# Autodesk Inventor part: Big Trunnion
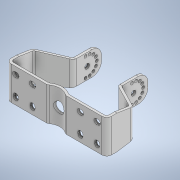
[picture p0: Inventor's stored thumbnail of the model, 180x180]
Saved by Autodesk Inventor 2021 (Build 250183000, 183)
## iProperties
Created: 2020-07
Part Number: Big Trunnion
Material: Generic
Document SubType Name: Modeling
Designer: DarrinWoodcock
Density: 1 g/cm^3
Appearance: Default
Title: 000
Author: Administrator
Revision Number: 1LAST_VERSION
Sending System: CREO PARAMETRIC BY PTC INC, 2018050
Preprocessor: CREO PARAMETRIC BY PTC INC, 2018050
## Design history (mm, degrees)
feature "Base1"
body "Solid1"
